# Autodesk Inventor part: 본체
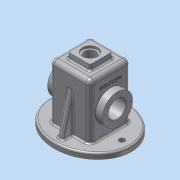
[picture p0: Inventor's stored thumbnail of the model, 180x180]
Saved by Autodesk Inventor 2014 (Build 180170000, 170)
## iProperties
Created: 2017-07
Part Number: 본체
Material: 알루미늄 6061
Document SubType Name: Modeling
Designer: 702-11
Density: 2.71 g/cm^3
Appearance: 알루미늄 - 평지
Mass: 947.78 g
Surface Area: 978.952 cm^2
Volume: 349.734 cm^3
Author: 702-11
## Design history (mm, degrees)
sketch "스케치1"
  geometry: L1 (0, 65)-(0, 0); L2 (0, 0)-(75, 0); 1 further point; 1 other entity
  constraints: 4 end point, 1 coincident, 1 horizontal, 1 vertical, 4 other
  dimensions: "d0" = 75 distance of L1.end L2.end; "d1" = 65 distance of L1.start L1.end
extrude "돌출1" new body sketch "스케치1" distance "d2" = 10; taper "d3" = 0 deg
sketch "스케치2"
  geometry: L1 (-37, -37)-(37, -37); L2 (37, -37)-(37, 37); L3 (37, 37)-(-37, 37); L4 (-37, 37)-(-37, -37); L5 (-37, -37)-(37, 37); L6 (37, -37)-(-37, 37); 1 further point; 1 other entity
  constraints: 12 end point, 2 midpoint, 2 parallel, 2 perpendicular, 1 horizontal, 1 other
  dimensions: "d4" = 74 distance of L3.end L1.start
extrude "돌출2" join sketch "스케치2" distance "d5" = 100; taper "d6" = 0 deg
sketch "스케치3"
  geometry: L1 (-32, -32)-(32, -32); L2 (32, -32)-(32, 32); L3 (32, 32)-(-32, 32); L4 (-32, 32)-(-32, -32); L5 (-32, -32)-(32, 32); L6 (32, -32)-(-32, 32); 1 further point; 1 other entity
  constraints: 12 end point, 2 midpoint, 2 parallel, 2 perpendicular, 1 horizontal, 1 other
  dimensions: "d7" = 64 distance of L1.end L2.end
extrude "돌출3" cut sketch "스케치3" distance "d8" = 105; taper "d9" = 0 deg
sketch "스케치4"
  geometry: L1 (-20, -20)-(20, -20); L2 (20, -20)-(20, 20); L3 (20, 20)-(-20, 20); L4 (-20, 20)-(-20, -20); L5 (-20, -20)-(20, 20); L6 (20, -20)-(-20, 20); 1 further point
  constraints: 12 end point, 2 midpoint, 2 parallel, 2 perpendicular, 1 horizontal
  dimensions: "d10" = 40 distance of L3.end L1.start
extrude "돌출4" join sketch "스케치4" distance "d11" = 10; taper "d12" = 0 deg
sketch "스케치5"
  geometry: L1 (-75, 0)-(-75, 10) reference; L2 (-75, 10)-(-37, 10) reference; L3 (-37, 10)-(-37, 110) reference; L4 (-37, 110)-(-20, 110) reference; L5 (-20, 110)-(-20, 120) reference; L6 (-20, 120)-(20, 120) reference; L7 (20, 120)-(20, 110) reference; L8 (20, 110)-(37, 110) reference; L9 (37, 110)-(37, 10) reference; L10 (37, 10)-(75, 10) reference; L11 (75, 10)-(75, 0) reference; L12 (75, 0)-(32, 0) reference; L13 (32, 0)-(32, 105) reference; L14 (32, 105)-(-32, 105) reference; L15 (-32, 105)-(-32, 0) reference; L16 (-32, 0)-(-75, 0) reference; L17 (-37, 55)-(37, 55); L18 (-37, 55)-(-50, 55); L19 (-50, 55)-(-50, 82.5); L20 (-50, 82.5)-(-37, 82.5); L21 (-37, 82.5)-(-37, 55); L22 (37, 55)-(50, 55); L23 (50, 55)-(50, 82.5); L24 (50, 82.5)-(37, 82.5); L25 (37, 82.5)-(37, 55); L26 (-37, 82.5)-(-32, 82.5); L27 (37, 82.5)-(32, 82.5); L28 (-25, 75.5)-(-25, 55); L29 (32, 82.5)-(25, 75.5); L30 (25, 75.5)-(25, 55); L31 (-25, 75.5)-(-32, 82.5); L32 (-32, 82.5)-(-32, 55); L33 (32, 82.5)-(32, 55); L34 (32, 0)-(32, 105) reference; 1 further point
  constraints: 34 end point, 10 point on line, 7 perpendicular, 5 parallel, 2 horizontal
  dimensions: "d13" = 55 distance between parallel lines of L12 L17; "d14" = 100 distance between parallel lines of L19 L23; "d15" = 13 distance of L23.end L24.end; "d16" = 55 diameter of L24 L17; "d18" = 55 diameter of L20 L17; "d19" = 7 distance between parallel lines of L15 L28; "d20" = 7 distance between parallel lines of L13 L30; "d21" = 135 deg angle of L13 L29; "d23" = 135 deg angle of L15 L31; "d24" = 55 diameter of L26.end L17 (derived); "d25" = 55 diameter of L27.end L17 (derived)
revolve "회전1" sketch "스케치5" stored, may be unused: angle "d26" = 90 deg
hole "구멍1" diameter "d29" = 32; stored, may be unused: countersink angle "d33" = 90 deg, drill point angle "d35" = 118 deg; dims "d27" = 10, "d28" = 10, "d30" = 6, "d31" = 4, "d32" = 2, "d34" = 8
sketch "스케치6"
  geometry: L1 (65, 10)-(65, 0) reference; L2 (65, 0)-(32, 0) reference; L3 (32, 0)-(32, 105) reference; L4 (32, 105)-(-32, 105) reference; L5 (-32, 105)-(-32, 0) reference; L6 (-32, 0)-(-65, 0) reference; L7 (-65, 0)-(-65, 10) reference; L8 (-65, 10)-(-37, 10) reference; L9 (-37, 10)-(-37, 110) reference; L10 (-37, 110)-(-20, 110) reference; L11 (-20, 110)-(-20, 120) reference; L12 (-20, 120)-(20, 120) reference; L13 (20, 120)-(20, 110) reference; L14 (20, 110)-(37, 110) reference; L15 (37, 110)-(37, 10) reference; L16 (37, 10)-(65, 10) reference; L17 (-55, 10)-(-37, 82.194); 1 further point
  constraints: 2 end point, 2 point on line
  dimensions: "d36" = 10 distance of L7.end L17.start; "d37" = 14 deg angle of L7 L17
feature "리브1" sketch "스케치6" dims "d38" = 1, "d39" = 10, "d40" = 0, "d41" = 0, "d42" = 1, "d43" = 1
sketch "스케치7"
  geometry: 2 further points
  constraints: 1 coincident
hole "구멍2" sketch "스케치7" at (0, 0) diameter "d44" = 21; stored, may be unused: countersink angle "d48" = 90 deg, drill point angle "d50" = 118 deg; dims "d45" = 6, "d46" = 28, "d47" = 4, "d49" = 8
sketch "스케치8"
  geometry: 2 further points; 1 other entity
  constraints: 1 horizontal alignment, 1 other
  dimensions: "d51" = 58 distance of point (0, 0) point (-58, 0)
hole "구멍3" sketch "스케치8" at (-58, 0) diameter "d52" = 10; stored, may be unused: countersink angle "d56" = 90 deg, drill point angle "d58" = 118 deg; dims "d53" = 6, "d54" = 28, "d55" = 4, "d57" = 8
sketch "스케치9" dims "d59" = 45
  geometry: C1 r 16 at (0, 0) reference; 3 further points
  constraints: 2 horizontal alignment, 1 coincident, 2 other
hole "구멍4" sketch "스케치9" at (22.5, 0) diameter "d60" = 3.242; stored, may be unused: countersink angle "d64" = 90 deg, drill point angle "d66" = 118 deg; dims "d61" = 8, "d62" = 28, "d63" = 4, "d65" = 10
fillet "모깎기1" dims "d71" = 3
fillet "모깎기2" dims "d72" = 8
fillet "모깎기7" dims "d85" = 3
fillet "모깎기3" dims "d73" = 8
feature "면 기울기2" dims angle "d81" = 5 deg
fillet "모깎기4" dims "d74" = 3
fillet "모깎기5" dims "d75" = 0.5
sketch "스케치10"
  geometry: L1 (-18, 12)-(-18, 46) reference; L2 (92, 66)-(0, 66) reference; 3 further points
  constraints: 1 other
  dimensions: "d77" = 30 distance from line of L1 point (12, 29); "d78" = 37 distance from line of L2 point (12, 29)
feature "엠보싱1" sketch "스케치10" dims "d0" = 75, "d1" = 65, "d7" = 64, "d79" = 0.5, "d80" = 0
chamfer "모따기1" distance "d82" = 1; stored, may be unused: second distance "d83" = 2, angle "d84" = 45 deg
node "솔리드1"
mirror "대칭1"
pattern_circular "원형 패턴1" dims angle "d68" = 360 deg
mirror "대칭2"
node "절단 모서리 투영1"
node "절단 모서리 투영2"
